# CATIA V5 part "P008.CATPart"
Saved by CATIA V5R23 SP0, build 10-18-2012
Part number: P008
Definition: Vis Chc M8x60
Description: ISO 4762 Vis Chc M8x60
Publications: "Mating Edge", "Axis"
Bounding box of the stored display mesh (mm): x -90 to 8, y -6.5 to 6.5, z -6.453 to 6.453
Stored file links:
  C:\wamp\www\COURS\CONCEPTION GMP1\TITRE 02-SEMESTRE 2\03-TP7-PRESSE MECANIQUE\eleve\P008.CATPart
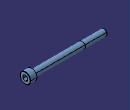
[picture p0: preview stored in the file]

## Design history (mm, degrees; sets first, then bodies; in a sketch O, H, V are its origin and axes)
Parameters
  Material = "St"
  d_dia = 8 mm
  l_nom = 90 mm
  k_head_depth_max = 8 mm
  s_nom = 6 mm
  r_min = 0.4 mm
  ds_max = 8 mm
  e = 6.86 mm
  t_min = 4 mm
  p_pitch = 1.25 mm
  Threading = 28 mm
  dk_max = 13 mm
  PartNumber = "ISO 4762 Vis Chc M8x60"
Body1 "PartBody" (main body)
  Sketch1 on yz-plane, origin (0, 0, 0), H (0, 1, 0), V (0, 0, 1)
    circle A1 centre (0, 0) radius 6.5
    radius A1 = 6.5 {= dk_max /2}
  Pad1: profile Sketch1, direction (1, 0, 0), length 8 {= k_head_depth_max}
  Fillet1: radius 0.4 {= r_min}, on edge [face of Pad1 | face of Pad1]
  Body2
    Sketch2 on face of Pad1, origin (8, 0, 0), H (0, 1, 0), V (0, 0, 1)
      point P1 (3, -1.7321)
      point P2 (3, 1.7321)
      point P3 (0, 3.4641)
      point P4 (-3, 1.7321)
      point P5 (-3, -1.7321)
      point P6 (0, -3.4641)
      point P7 (3, 0)
      line L1 (3, -1.7321) -> (3, 1.7321)
      line L2 (3, 1.7321) -> (0, 3.4641)
      line L3 (0, 3.4641) -> (-3, 1.7321)
      line L4 (-3, 1.7321) -> (-3, -1.7321)
      line L5 (-3, -1.7321) -> (0, -3.4641)
      line L6 (0, -3.4641) -> (3, -1.7321)
      construction line L7 (0, 0) -> (3, 0)
      construction circle A1 centre (0, 0) radius 3.4641
      construction arc A2 centre (-3, -1.7321) radius 3.4641 from (-3, 1.7321) to (0, -3.4641) cw
      construction arc A3 centre (3, 1.7321) radius 3.4641 from (0, 3.4641) to (3, -1.7321) ccw
      point P8 (-3, -1.7321)
      point P9 (3, 1.7321)
      distance L1 L4 = 6 {= s_nom}
      horizontal: L7 H
      coincidence: A1 P1, A1 P2, A1 P3, A1 P4, A1 P5, A1 P6, A2 P4, A2 P6, A2 O, P8 P5, A3 P3, A3 P1, A3 O, P9 P2
      midpoint: P7 L1
    Pad2: profile Sketch2, direction (-1, 0, 0), length 5.9769 {= t_min +(e /3.47)}
    Body3
      Sketch3 on zx-plane, origin (0, 0, 0), H (-1, 0, 0), V (0, 0, 1)
        point P1 (-2.0197, 0)
        line L1 (-2.0197, 0) -> (-4, 3.43)
        line L2 (-4, 3.43) -> (-8, 3.43)
        line L3 (-8, 3.43) -> (-8, 0)
        axis line L4 (-46.2384, 0) -> (26.3409, 0)
        reference projected line E1 (-8, -6.9227) -> (-8, 6.9227) from edge [face of Pad2 | face of Pad2]
        length L2 = 4 {= t_min}
        angle L1 L4 = 60
        distance L2 L4 = 3.43 {= e /2}
        horizontal: L2 H, L4 H
        perpendicularity: L3 L2
        fix: L4
        coincidence: L3 E1, P1 L4
      Shaft1: profile Sketch3, axis Sketch3.L4, angle 360
    Intersect1: tool Body3
  Remove1: tool Body2
  Sketch4 on xy-plane, origin (0, 0, 0), H (1, 0, 0), V (0, 1, 0)
    line L1 (0, 0) -> (0, 4)
    line L2 (0, 4) -> (-62, 4)
    line L3 (-62, 4) -> (-62, 3.9024)
    line L4 (-62, 3.9024) -> (-90, 3.9024)
    line L5 (-90, 3.9024) -> (-90, 0)
    axis line L6 (-192.3446, 0) -> (99.1594, 0)
    distance L5 L1 = 90 {= l_nom}
    distance L3 L5 = 28 {= Threading}
    distance L2 L6 = 4 {= ds_max /2}
    distance L4 L6 = 3.9024 {= d_dia /2.05}
    vertical: L1 V, L3 V, L5 V
    horizontal: L2 H, L4 H, L6 H
    fix: L6
  Shaft2: profile Sketch4, axis Sketch4.L6, angle 360
  Fillet2: radius 0.4 {= r_min}, on edge [face of Shaft2 | face of Pad1]
  Chamfer1: length 1.25 {= p_pitch}, angle 45, on edge [face of Shaft2 | face of Shaft2]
